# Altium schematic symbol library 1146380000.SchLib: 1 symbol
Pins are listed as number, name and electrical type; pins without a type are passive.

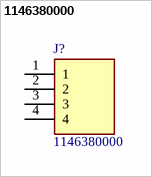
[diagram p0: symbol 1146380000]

## 1146380000
designator J?
PCB plug-in connector, male header, open side, THT solder connection, 5.08 mm, Number of poles: 4, 180, Solder pin length: 3.2 mm, tinned, orange, Box; Manufacturer_Name: Weidmuller; Geometry.Height: 12mm
footprint SHDR4W120P0X508_1X4_2012X850X1200P
pins: 1, 2, 3, 4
